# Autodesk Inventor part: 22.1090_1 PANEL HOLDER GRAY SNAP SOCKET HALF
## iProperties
Created: 2007-04
Part Number: 22.1090_1 PANEL HOLDER GRAY SNAP SOCKET HALF
Document SubType Name: Modeling
Designer: Andy Moles
Material: PVC-U
Density: 1.4 g/cm^3
Author: Andy Moles
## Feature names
1. Extrusion1
